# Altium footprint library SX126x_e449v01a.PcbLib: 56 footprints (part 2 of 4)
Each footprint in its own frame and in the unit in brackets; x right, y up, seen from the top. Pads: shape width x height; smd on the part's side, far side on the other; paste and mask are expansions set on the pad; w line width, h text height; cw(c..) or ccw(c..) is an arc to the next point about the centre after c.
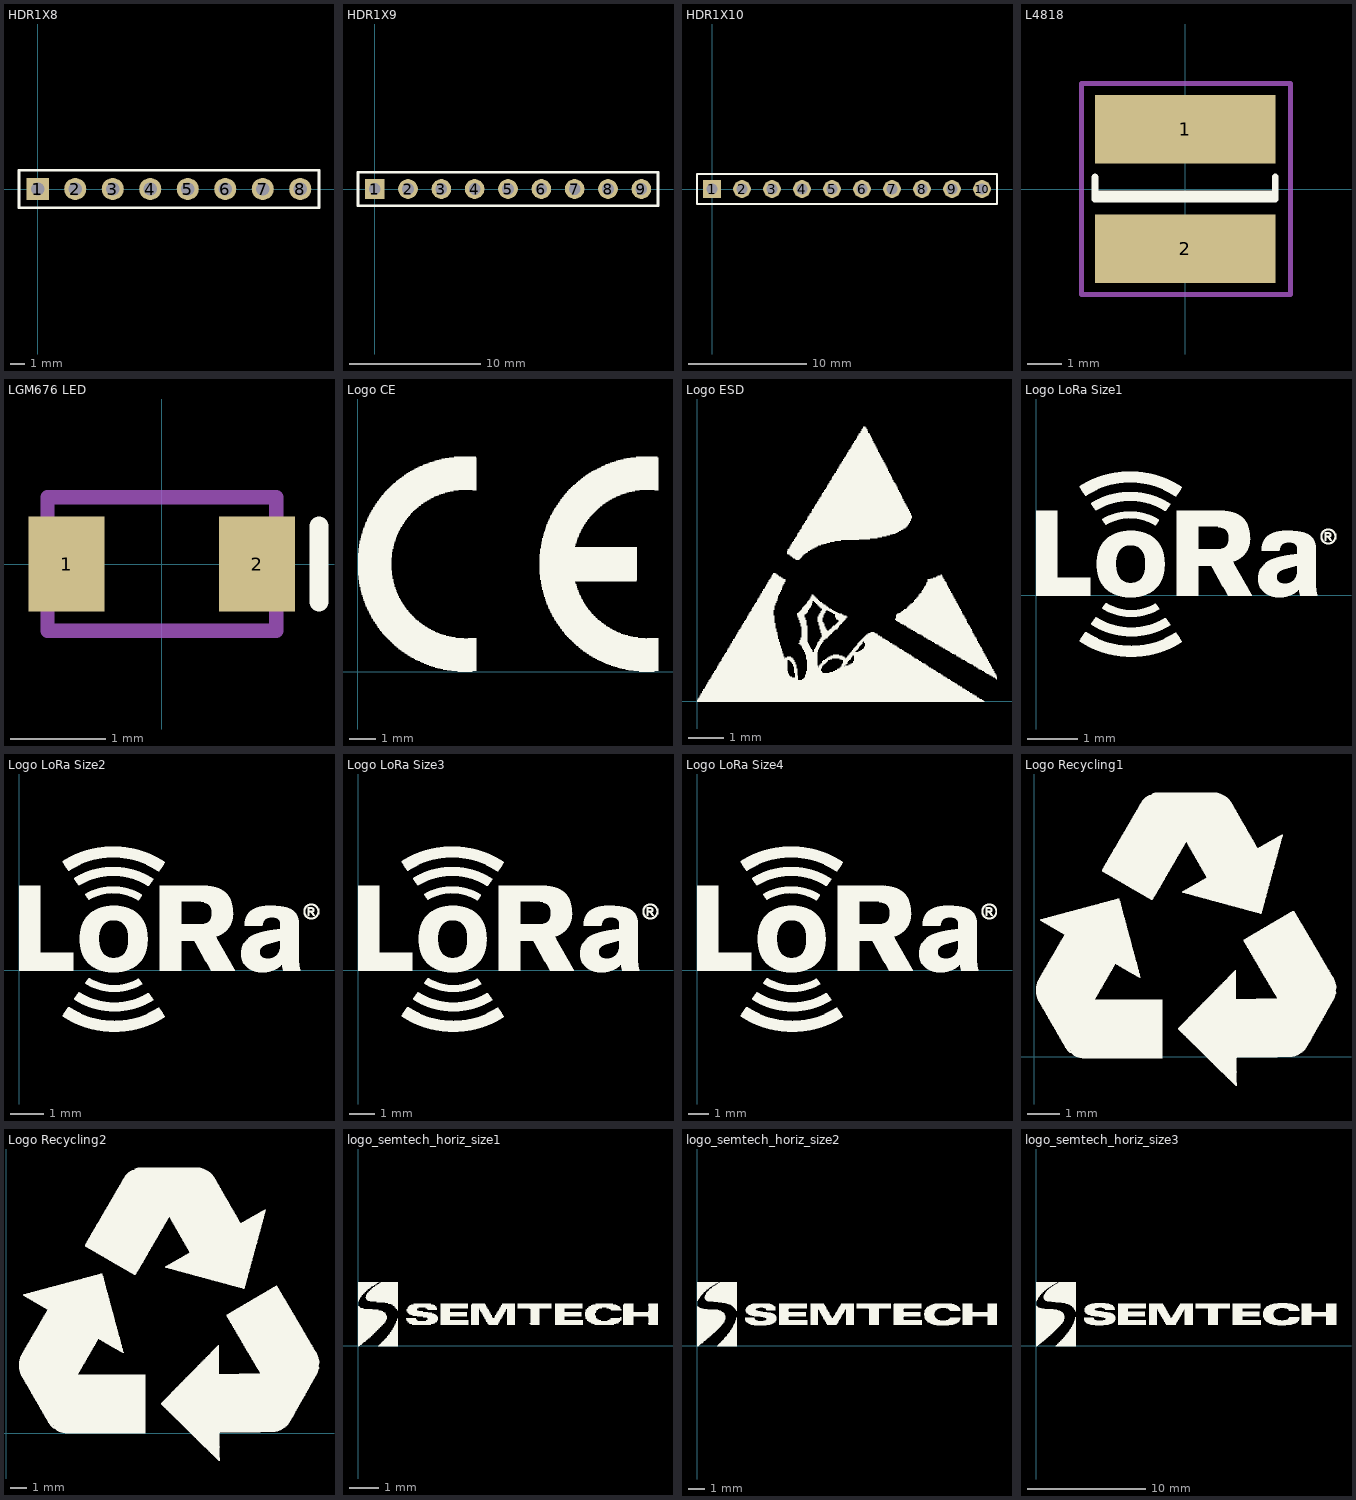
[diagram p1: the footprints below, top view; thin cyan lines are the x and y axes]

## HDR1X8 [mm] "Connector; Header; 8 Position"
pads (8):
  rect 1.5x1.5 hole 0.9: 1(0,0)
  round 1.5 hole 0.9: 2(2.54,0) 3(5.08,0) 4(7.62,0) 5(10.16,0) 6(12.7,0) 7(15.24,0) 8(17.78,0)
Top Overlay:
  lines w0.2: -1.27,-1.27 19.05,-1.27 19.05,1.27 -1.27,1.27 -1.27,-1.27

## HDR1X9 [mm] "Connector; Header; 9 Position"
pads (9):
  rect 1.5x1.5 hole 0.9: 1(0,0)
  round 1.5 hole 0.9: 2(2.54,0) 3(5.08,0) 4(7.62,0) 5(10.16,0) 6(12.7,0) 7(15.24,0) 8(17.78,0) 9(20.32,0)
Top Overlay:
  lines w0.2: -1.27,-1.27 21.59,-1.27 21.59,1.27 -1.27,1.27 -1.27,-1.27

## HDR1X10 [mm] "Connector; Header; 10 Position"
pads (10):
  rect 1.5x1.5 hole 0.9: 1(0,0)
  round 1.5 hole 0.9: 2(2.54,0) 3(5.08,0) 4(7.62,0) 5(10.16,0) 6(12.7,0) 7(15.24,0) 8(17.78,0) 9(20.32,0) 10(22.86,0)
Top Overlay:
  lines w0.2: -1.27,-1.27 -1.27,1.27 0.635,1.27 24.13,1.27 24.13,-1.27 -1.27,-1.27

## L4818 [mil] "L4818"
height 196.85
pads (2):
  rect 209x79 smd mask+1.97: 1(0,69.03) 2(0,-69.03)
Top Overlay:
  lines w7.87: -104.33,-0.98 -104.33,-5.91 104.33,-5.91 ; -104.33,13.78 -104.33,-11.81 104.33,-11.81 104.33,13.78
Mechanical 15:
  lines w5.91: -120.08,-122.05 122.05,-122.05
  lines w6: -120.08,-122.05 -120.08,122.05 122.05,122.05 122.05,-122.05

## LGM676 LED [mm] "Chip Diode; Body 2.1 x 1.4 mm (LxW typ)"
height 1.1
pads (2):
  rect 0.8x1 smd mask+0.05: 1(-1,0) 2(1,0)
Top Overlay:
  lines w0.2: 1.65,-0.4 1.65,0.4
Mechanical 15:
  lines w0.15: -1.2,-0.7 1.2,-0.7 1.2,0.7 -1.2,0.7 -1.2,-0.7
3D body: height 12, standoff 0, extent -1.2,-0.7 1.2,0.7

## Logo CE [mm] "Logo CE"
height 0.1
Top Overlay:
  drawing of 654 lines, arcs and shapes, not listed

## Logo ESD [mm] "Logo ESD"
height 0.1
Top Overlay:
  drawing of 682 lines, arcs and shapes, not listed

## Logo LoRa Size1 [mm] "Logo LoRa Size1 - Top Overlay - 6x4mm - Registered"
Top Overlay:
  drawing of 1298 lines, arcs and shapes, not listed

## Logo LoRa Size2 [mm] "Logo LoRa Size2 - Top Overlay - 9x5.5mm - Registered"
Top Overlay:
  drawing of 1298 lines, arcs and shapes, not listed

## Logo LoRa Size3 [mm] "Logo LoRa Size3 - Top Overlay - 14.5x8mm - Registered"
Top Overlay:
  drawing of 1298 lines, arcs and shapes, not listed
3D body: height 0.8, standoff 0.1, extent 2.3,-0.1 5.25,2.65

## Logo LoRa Size4 [mm] "Logo LoRa Size4 - Top Overlay - 18x9.5mm - Registered"
Top Overlay:
  drawing of 1298 lines, arcs and shapes, not listed

## Logo Recycling1 [mm] "Logo Recycling1"
height 0.1
Top Overlay:
  drawing of 3302 lines, arcs and shapes, not listed

## Logo Recycling2 [mm] "Logo Recycling2"
height 0.1
Top Overlay:
  drawing of 3309 lines, arcs and shapes, not listed

## logo_semtech_horiz_size1 [mm] "Logo semtech horizontal - size1 - S"
Top Overlay:
  drawing of 453 lines, arcs and shapes, not listed

## logo_semtech_horiz_size2 [mm] "Logo semtech horizontal - size2 - M"
Top Overlay:
  drawing of 790 lines, arcs and shapes, not listed

## logo_semtech_horiz_size3 [mm] "Logo semtech horizontal - size3 - L"
Top Overlay:
  drawing of 1137 lines, arcs and shapes, not listed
